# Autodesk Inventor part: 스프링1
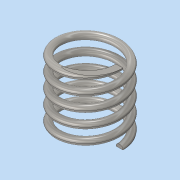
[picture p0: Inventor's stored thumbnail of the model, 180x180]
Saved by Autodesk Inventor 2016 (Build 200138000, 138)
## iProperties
Created: 2019-11
Part Number: 스프링1
Material: 스테인레스 스틸
Document SubType Name: Modeling
Designer: user
Density: 8 g/cm^3
Appearance: 반연마
Mass: 6.57569 g
Surface Area: 16.7185 cm^2
Volume: 0.821961 cm^3
Author: user
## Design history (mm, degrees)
sketch "스케치1"
  geometry: L1 (0, 0)-(8.5, 0); L2 (8.5, 0)-(8.5, 20.5); L3 (8.5, 20.5)-(0, 20.5); L4 (0, 20.5)-(0, 0); C1 r 1 at (8.5, 0)
  constraints: 8 end point, 2 parallel, 1 centre point, 1 coincident, 1 horizontal, 1 perpendicular
  dimensions: "d0" = 17 diameter of L2 L4; "d1" = 20.5 distance between parallel lines of L1 L3 (derived); "d2" = 2 diameter of C1
feature "코일1" sketch "스케치1" pitch "d3" = 10; turns "d5" = 5; dims "d4" = 20.5 (= d1), "d6" = 0, angle "d7" = 90 deg, angle "d8" = 90 deg, "d9" = 0, "d10" = 0
sketch "스케치2"
  geometry: L1 (20.5, 11.695)-(0, 11.695); L2 (0, 11.695)-(0, -11.695); L3 (0, -11.695)-(20.5, -11.695); L4 (20.5, -11.695)-(20.5, 11.695); 2 further points
  constraints: 8 end point, 2 parallel, 1 coincident, 1 horizontal, 1 midpoint, 1 perpendicular
  dimensions: "d11" = 20.5 distance between parallel lines of L2 L4 (= d1)
extrude "돌출1" sketch "스케치2" stored distance "d12" = 42; taper "d13" = 0 deg
node "솔리드1"
